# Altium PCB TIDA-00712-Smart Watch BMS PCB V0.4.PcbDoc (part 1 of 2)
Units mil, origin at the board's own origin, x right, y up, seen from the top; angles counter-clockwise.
Board outline 1150 x 800 mil, 2 copper layers (Top Layer, Bottom Layer), stack 11.461 mil thick; 83 components, 53 nets, 288 pads, 152 vias.
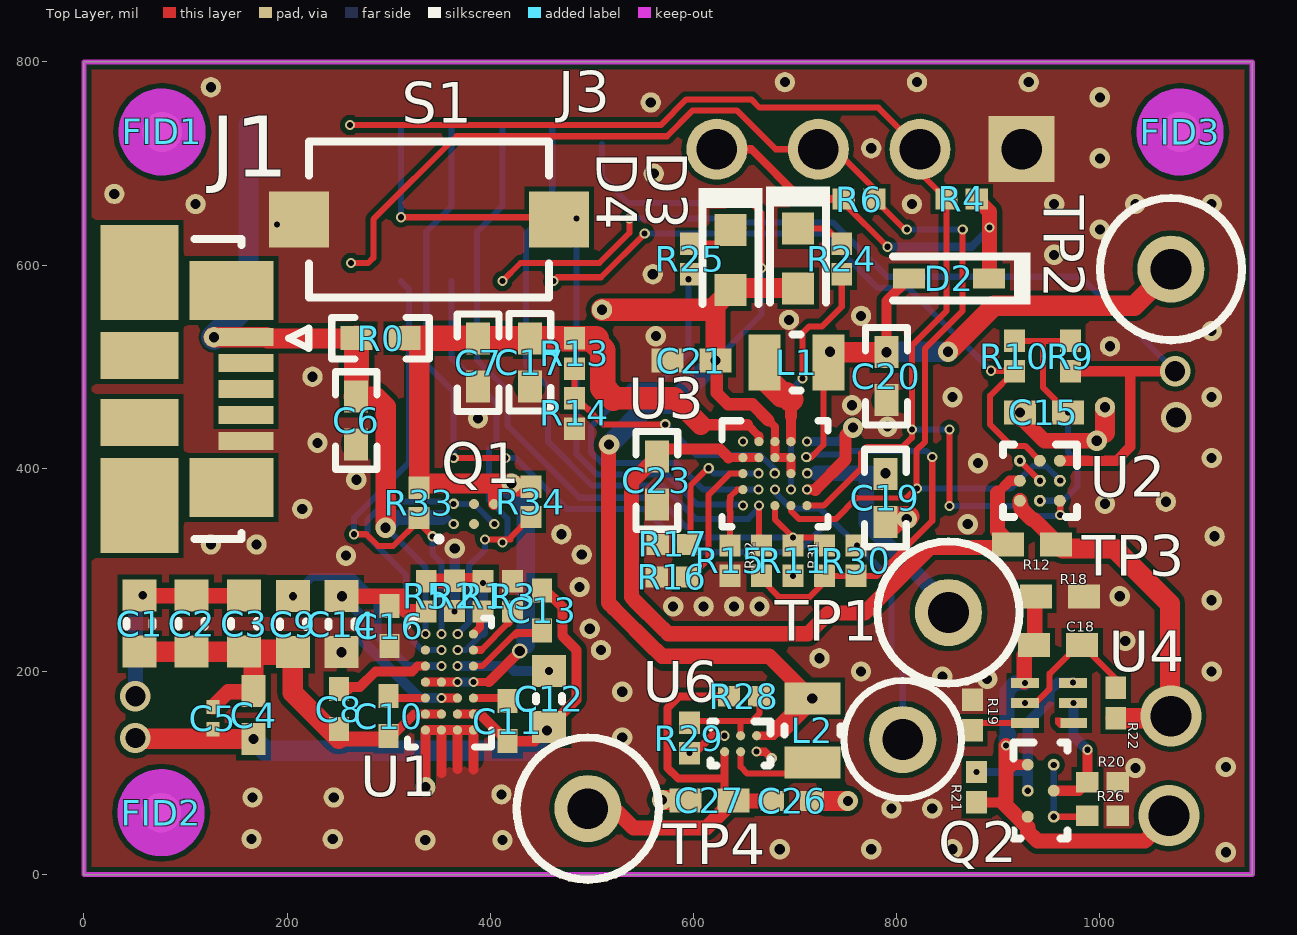
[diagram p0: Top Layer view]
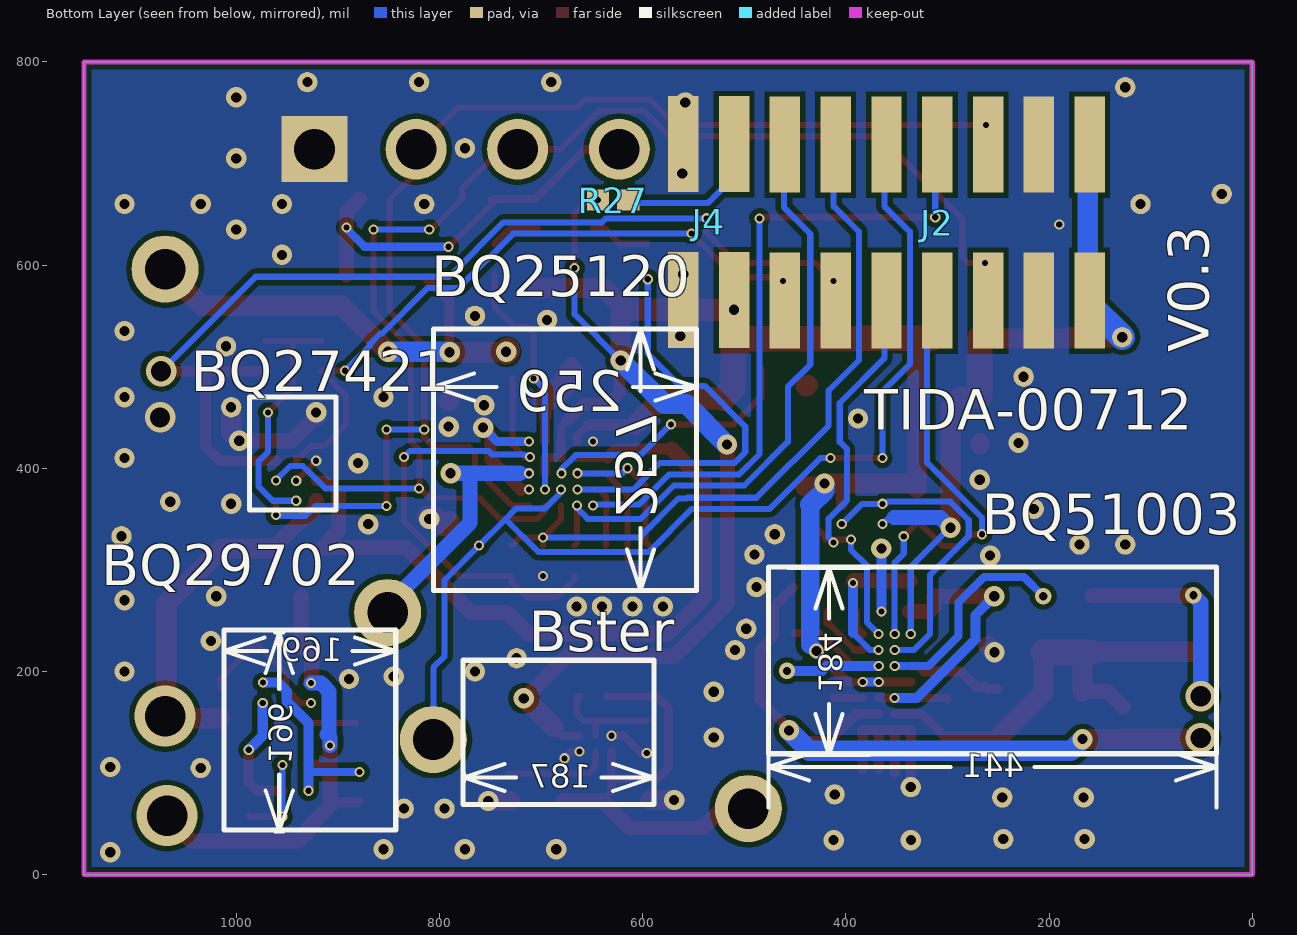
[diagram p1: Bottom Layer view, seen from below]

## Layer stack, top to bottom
Top Solder: solder mask 0.4, Solder Resist, Dk 3.5
Top Layer: signal copper 1.4
Dielectric1: core 8.661, FR-4, Dk 4.8
Bottom Layer: signal copper 1.4
Bottom Solder: solder mask 0.4, Solder Resist, Dk 3.5

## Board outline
0,0 1150,0 1150,800 0,800

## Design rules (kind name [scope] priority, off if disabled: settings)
AcuteAngle [All] p1: minimum=4.50000000000000E+0001 checktracksonly=FALSE
AssemblyTestPointUsage [All] p1: valid=2
Clearance Clearance_Keepouts [All] p1: gap=5
Clearance Clearance_BoardEdge_MountingHoles [All] p2: gap=5
Clearance Clearance_BoardEdge_Poly [All] p3: gap=5
Clearance Clearance_BoardEdge [All] p4: gap=4 except(0: Via-Via Poly-Poly SMDPad-Via Arc-Via Track-Via THPad-Via)
Clearance Clearance_Poly [All] p5: gap=5
ComponentClearance ComponentClearance_MountingHoles_FiducialMarks [InComponentClass('Mounting Holes') vs InComponentClass('FiducialMark')] p1: gap=50 collisioncheckmode=3 verticalgap=10 showdistances=FALSE
ComponentClearance ComponentClearance_Shunt [InComponentClass('Header') vs InComponentClass('Shunt')] p2: gap=50 collisioncheckmode=3 verticalgap=0 showdistances=FALSE
ComponentClearance ComponentClearance_Logo [InComponentClass('Logo')] p3: gap=10 collisioncheckmode=3 verticalgap=10 showdistances=FALSE
ComponentClearance ComponentClearance_ScrewToNut [(HasFootprint('NY PMS 440 0025 PH')) vs (HasFootprint('Keystone_1902C'))] p4: gap=50 collisioncheckmode=3 verticalgap=10 showdistances=FALSE
ComponentClearance ComponentClearance_MountingHoles [InComponentClass('Mounting Holes')] p5: gap=10 collisioncheckmode=3 verticalgap=100000 showdistances=FALSE
ComponentClearance ComponentClearance_SmallPassives [HasFootprint('0201*') or HasFootprint('0402*') or HasFootprint('0508') or HasFootprint('0603*') or HasFootprint('0612') or HasFootprint('0805*') or HasFootprint('0815*') or HasFootprint('0830*') or HasFootprint('1206*') or HasFootprint('1210*') or HasFootprint('1808*') or HasFootprint('1812*') or HasFootprint('1825*') or HasFootprint('2010*') or HasFootprint('2220*') or HasFootprint('2225*') or HasFootprint('2512*') or HasFootprint('2728*') or HasFootprint('3518*') vs HasFootprint('0201*') or HasFootprint('0402*') or HasFootprint('0508') or HasFootprint('0603*') or HasFootprint('0612') or HasFootprint('0805*') or HasFootprint('0815*') or HasFootprint('0830*') or HasFootprint('1206*') or HasFootprint('1210*') or HasFootprint('1808*') or HasFootprint('1812*') or HasFootprint('1825*') or HasFootprint('2010*') or HasFootprint('2220*') or HasFootprint('2225*') or HasFootprint('2512*') or HasFootprint('2728*') or HasFootprint('3518*')] p6: gap=10 collisioncheckmode=3 verticalgap=10 showdistances=FALSE
ComponentClearance ComponentClearance_THtoSMT [IsThruComponent vs IsSMTComponent] p7: gap=10 collisioncheckmode=3 verticalgap=30 showdistances=FALSE
ComponentClearance ComponentClearance_THtoTH [IsThruComponent vs IsThruComponent] p8: gap=10 collisioncheckmode=3 verticalgap=30 showdistances=FALSE
ComponentClearance [All] p9: gap=5 collisioncheckmode=3 verticalgap=10 showdistances=FALSE
DiffPairsRouting [All] p1: maxlimit=100 minlimit=10 mostfreqgap=10 toplayer_minwidth=15 toplayer_maxwidth=15 toplayer_prefwidth=15 bottomlayer_minwidth=15 bottomlayer_maxwidth=15 bottomlayer_prefwidth=15 maxuncoupledlength=1000
FabricationTestPointUsage TestPointUsage [All] p1: valid=2 allowmultiple=FALSE
FabricationTestpoint Testpoint [All] p1: side=3 testpointundercomponent=TRUE minsize=40 maxsize=100 preferedsize=60 minholesize=0 maxholesize=40 preferedholesize=32 testpointgrid=1 allowsidetop=TRUE allowsidebottom=TRUE usegrid=TRUE gridtolerance=0.01
FanoutControl Fanout_LCC [IsLCC] p1: bgadir=Out bgaviamode=Centered fanoutstyle=Auto fanoutdirection=Alternating viagrid=1 // Fanout_LCC (Default Rule)
FanoutControl Fanout_BGA [IsBGA] p2: bgadir=Out bgaviamode=Centered fanoutstyle=Auto fanoutdirection=Alternating viagrid=1 // Fanout_BGA (Default Rule)
FanoutControl Fanout_Default [All] p4: bgadir=Out bgaviamode=Centered fanoutstyle=Auto fanoutdirection=Alternating viagrid=1 // Fanout_Default (Default Rule)
FanoutControl Fanout_Small [(CompPinCount < 5)] p5: bgadir=Out bgaviamode=Centered fanoutstyle=Auto fanoutdirection=OutThenIn viagrid=1 // Fanout_Small (Default Rule)
HoleSize [All] p1: absolutevalues=TRUE maxlimit=251 minlimit=8 maxpercent=80.000 minpercent=20.000
MinimumAnnularRing MinimumAnnularRing_ThermalPadVias [IsVia and InAnyComponent] p1: minimumring=5.91
MinimumAnnularRing [All] p2: minimumring=9
MinimumSolderMaskSliver MinimumSolderMaskSliver_Logo [InComponentClass('Logo') vs InComponentClass('Logo')] p1: minsoldermaskwidth=0.7
MinimumSolderMaskSliver [All] p2: minsoldermaskwidth=3.94
PlaneClearance [All] p1: clearance=10
PlaneConnect [All] p1: planeconnectstyle=Relief reliefexpansion=10 reliefentries=4 reliefconductorwidth=10 reliefairgap=10
PolygonConnect [All] p1: connectstyle=Direct reliefconductorwidth=10 reliefentries=4 polygonreliefangle="90 Angle" airgapwidth=5
RoutingVias ThermalPadVias [IsVia and InAnyComponent] p1: holewidth=6 width=20 viastyle="Through Hole" minholewidth=6 minwidth=20 maxholewidth=15 maxwidth=30
RoutingVias [All] p2: holewidth=6 width=15 viastyle="Through Hole" minholewidth=6 minwidth=10 maxholewidth=10 maxwidth=15
SilkToBoardRegionClearance [Not ((IsComment or IsDesignator) And (Hide <> 'False')) and not InRegion(1000,500,4000,800)] p1:
SilkToSilkClearance SilkToSilkClearance_Pb-FreeLogo [(HasFootprint('Pb-Free_Overlay_Medium') OR HasFootprint('Pb-Free_Overlay_Small')) vs (HasFootprint('Pb-Free_Overlay_Medium') OR HasFootprint('Pb-Free_Overlay_Small'))] p1: silktosilkclearance=0
SilkToSilkClearance [All] p2: silktosilkclearance=4
SilkToSolderMaskClearance "Silk to Solder Mask Opening" [All] p1: minsilkscreentomaskgap=4 clearancetoexposedcopper=FALSE
SolderMaskExpansion [All] p1: expansion=1.97
UnpouredPolygon [All] p1: allowunpoured=FALSE
Width [All] p1: maxlimit=100 minlimit=6 preferedwidth=10 checkconnectedcopper=TRUE
13 further rules are at their usual default settings.

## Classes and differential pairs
component class Header: J2 J4
component class "TIDA-00712-Smart Watch BMS SCH V0.3": C1 C2 C3 C4 C5 C6 C7 C8 C9 C10 C11 C12 C13 C14 C15 C16 C17 C18 C19 C20 C21 C23 C26 C27 D2 D3 D4 J1 J2 J3 J4 L1 L2 Q1 Q2 R0 R1 R2 R3 R4 R5 R6 R8 R9 R10 R11 R12 R13 R14 R15 R16 R17 R18 R19 R20 R21 R22 R24 R25 R26 R27 R28 R29 R30 R31 R32 R33 R34 S1 TP1 TP2 TP3 TP4 U1 U2 U3 U4 U6
component class FiducialMark: FID1 FID2 FID3
component class AssemblyNote: ZZ1 ZZ2 ZZ3
component class "TIDA-00712-Smart Watch BMS Hardwere V0.3": FID1 FID2 FID3 ZZ1 ZZ2 ZZ3

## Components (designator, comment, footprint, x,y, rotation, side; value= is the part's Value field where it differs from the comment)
C1 "GRM188R71E683KA01D" 0603L 55,247 r90 top
C2 "GRM188R71E683KA01D" 0603L 106,247 r90 top
C3 "06033C473JAT2A" 0603L 157.75,247 r90 top
C4 "GRM155R71H182KA01D" 0402 167,157 r270 top
C5 "GRM033R71E101KA01D" 0201L 127,154 r90 top
C6 "GRM155R61C475ME11D" 0402 268,447 r270 top
C7 "CL05A106MP5NUNC" 0402 388,504 r270 top
C8 "GRM155R71E223KA61D" 0402L 251,163 r270 top
C9 "GRM188R71E474KA12D" 0603L 205.75,246.5 r270 top
C10 "GRM155R71E103KA01D" 0402L 300,156 r270 top
C11 "GRM155R71E103KA01D" 0402L 417,151 r270 top
C12 "GRM188R71E474KA12D" 0603L 458,173 r270 top
C13 "GRM155R71E223KA61D" 0402L 451,260 r90 top
C14 "EMK107BBJ106MA-T" 0603L 253.75,246.5 r90 top
C15 "GRM155R60J474KE19D" 0402 945,455 r180 top
C16 "GRM188R61C475KAAJ" 0402L 300.75,244.5 r270 top
C17 "GRM155R61A105KE15D" 0402 439,504.24 r270 top
C18 "GRM155R61A105KE15D" 0402 959,226 r180 top
C19 "CL05A106MP5NUNC" 0402 789,370.75 r270 top
C20 "CL05A106MP5NUNC" 0402 790,490.62 r270 top
C21 "GRM155R61C475ME11D" 0402 598,506 r0 top
C23 "GRM155R61A105KE15D" 0402 564,388 r270 top
C26 "GRM188R61C475KAAJ" 0402L 697,72.49 r0 top
C27 "GRM155R71C104KA88D" 0402 616,73 r180 top
D2 "1N4148WT" Fairchild_SOD-523F 851.63,587 r180 top
D3 "LTST-C190GKT" LED_LTST-C190 703,606.53 r90 top
D4 "LTST-C190CKT" LED_LTST-C190_Red 636.44,605 r90 top
FID1 "Fiducial" Fiducial10-20 77,731 r0 top
FID2 "Fiducial" Fiducial10-20 76,61 r0 top
FID3 "Fiducial" Fiducial10-20 1079,731 r0 top
J1 "47346-1001" Molex_47346-1001 -2.09,477.97 r270 top
J2 "20021121-00014T4LF" FCI_20021121-00014x4 310,641.77 r270 bottom
J3 "" CONN_22-05-3041 773,938.41 r180 top
J4 "20021121-00004C4LF" FCI_20021121-00004C4LF 535,642.23 r270 bottom
L1 "MDT2012-CLR2R2AM" MDT2012-CLR 701.5,504 r0 top
L2 "MDT2012-CLR2R2AM" MDT2012-CLR 717,142 r270 top
Q1 "CSD75208W1015" YZC0006ABBB 384,355 r90 top
Q2 "CSD83325L" YJE0006A 941.83,82.59 r0 top
R0 "CRCW04024K99FKED" 0402 292,528 r0 top
R1 "CRCW0201845RFKED" 0201M 393,274 r90 top
R2 "CRCW0201196RFKED" 0201M 364.75,274.5 r90 top
R3 "MCR006YRTF1002" 0201M 422,274 r270 top
R4 "CRCW020120K0FKED" 0201M 864,665 r180 top
R5 "CRCW020120K0FKED" 0201M 337,274 r90 top
R6 "CRCW020120K0FKED" 0201M 763,665 r0 top
R9 "CRCW020120K0FKED" 0201M 971,510.44 r270 top
R10 "CRCW020120K0FKED" 0201M 916,510.44 r270 top
R11 "CRCW020120K0FKED" 0201M 698,308.96 r90 top
R12 "CRCW04024K99FKED" 0402 933,325 r0 top
R13 "CRCW020120K0FKED" 0201M 483,513 r90 top
R14 "CRCW020120K0FKED" 0201M 483,454 r90 top
R15 "CRCW020120K0FKED" 0201M 636,308.96 r90 top
R16 "CRCW020120K0FKED" 0201M 579,293 r0 top
R17 "CRCW020120K0FKED" 0201M 580,325 r0 top
R18 "CRCW04024K99FKED" 0402 960.62,274 r180 top
R19 "CRCW020120K0FKED" 0201M 874.62,157.08 r270 top
R20 "CRCW020120K0FKED" 0201M 1002.62,91 r180 top
R21 "CRCW020120K0FKED" 0201M 878.62,86.04 r270 top
R22 "CRCW020120K0FKED" 0201M 1015.62,169 r90 top
R24 "CRCW020120K0FKED" 0201M 746,606 r90 top
R25 "CRCW020120K0FKED" 0201M 597,606 r90 top
R26 "ERJ-1GEJ1R2C" 0201M 1002.66,58 r0 top
R27 "ERJ-1GEJ1R2C" 0201M 629,664 r180 bottom
R28 "CRCW020120K0FKED" 0201M 650,175.49 r180 top
R29 "CRCW020120K0FKED" 0201M 596,134.49 r90 top
R30 "CRCW020120K0FKED" 0201M 760,309.04 r90 top
R31 "CRCW020120K0FKED" 0201M 729,308.96 r90 top
R32 "CRCW020120K0FKED" 0201M 667,308.96 r270 top
R33 "CRCW020120K0FKED" 0201M 330,366 r270 top
R34 "CRCW020120K0FKED" 0201M 440,367 r270 top
S1 "434121025816" SW_434121025816 339.95,645 r0 top
TP1 "5003" Keystone5003 806,133 r0 top
TP2 "5005" Keystone5005 1070,596 r0 top
TP3 "5005" Keystone5005 851,258 r0 top
TP4 "5005" Keystone5005 496,65 r0 top
U1 "BQ51003YFPR" YFP0028APAL 359.75,189.5 r180 top
U2 "BQ27421YZFR-G1B" YZF0009AKAL 941,387.68 r270 top
U3 "BQ25120YFF" YFF0025AWAW 680.2,394.67 r0 top
U4 "BQ29702DSER" DSE0006A 950.08,169 r180 top
U6 "TPS61046YFFR" YFF0006AAAA 646.47,128.86 r270 top
ZZ1 "These assemblies are ESD sensitive, ESD precautions shall be observed." AssemblyNote 185,3829.11 r0 top
ZZ2 "These assemblies must be clean and free from flux and all contaminants. Use of no clean flux is not acceptable." AssemblyNote 185,3740.56 r0 top
ZZ3 "These assemblies must comply with workmanship standards IPC-A-610 Class 2, unless otherwise specified." AssemblyNote 185,3652 r0 top

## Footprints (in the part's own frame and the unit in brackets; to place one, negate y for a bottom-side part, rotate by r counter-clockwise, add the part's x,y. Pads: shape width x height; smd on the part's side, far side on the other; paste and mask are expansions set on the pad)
0201L [mm] "Data from Kemet datasheet CC101_COM dated 7/28/11"
  rect 0.36x0.32 smd mask+0.048: 1(-0.28,0) 2(0.28,0)
  body extent -0.31,-0.16 0.31,0.16, height 0.26
0201M [mm] "Data from Kemet datasheet CC101_COM dated 7/28/11"
  rect 0.56x0.52 smd mask+0.048: 1(-0.38,0) 2(0.38,0)
  body extent -0.31,-0.16 0.31,0.16, height 0.26
0402 [mm] "0402 from SM-752 data"
  rect 0.8x0.6 smd: 1(-0.6,0) 2(0.6,0)
  body extent -0.55,-0.3 0.55,0.3, height 0.6
0402L [mm] "0402 from SM-752 data"
  rect 0.6x0.5 smd: 1(-0.5,0) 2(0.5,0)
  body extent -0.55,-0.3 0.55,0.3, height 0.6
0603L [mm] "0603 from SM-752 data"
  rect 0.8x0.85 smd: 1(-0.7,0) 2(0.7,0)
  silkscreen extent -0.07,-0.33 0.07,0.33, body extent -0.87,-0.47 0.87,0.47, height 0.85
AssemblyNote [mil] "Assembly Note"
CONN_22-05-3041 [mil] "MOLEX"
  rect 64.96x64.96 hole 40: 1(-150,224.41)
  round 60 hole 40: 2(-50,224.41) 3(50,224.41) 4(150,224.41)
  body extent -197,-272 197,237, height 251
DSE0006A [mm] "TI recommended land pattern"
  rect 0.66x0.25 smd: 1(-0.62,0.5)
  rect 0.7x0.25 smd: 2(-0.6,0) 3(-0.6,-0.5) 4(0.6,-0.5) 5(0.6,0) 6(0.6,0.5)
  Top Layer region: -0.3,0.625 -0.25,0.625 -0.15,0.525 -0.15,0.375 -0.3,0.375
  body extent -0.77,-0.77 0.77,0.77, height 0.8
Fairchild_SOD-523F [mm] "SMD, 2-Leads, Body 1.2x0.8mm"
  rect 0.8x0.5 smd: 1(-1,0) 2(1,0)
  silkscreen extent -2.03,-0.65 1.4,0.65, body extent -0.65,-0.45 0.65,0.45, height 0.7
FCI_20021121-00004C4LF [mm] "SMD, 4-Leads, Body 2.54x3.4mm, Pitch 1.27mm"
  rect 2.4x0.76 smd: 1(-1.95,0.635) 2(1.95,0.635) 3(-1.95,-0.635) 4(1.95,-0.635)
  body extent -2.8,-1.27 2.7,1.27, height 4.5
FCI_20021121-00014x4 [mm] "Header, 1.27mm, 7x2, SMT"
  rect 2.4x0.76 smd: 1(-1.95,3.81) 2(1.95,3.81) 3(-1.95,2.54) 4(1.95,2.54) 5(-1.95,1.27) 6(1.95,1.27) 7(-1.95,0) 8(1.95,0) 9(-1.95,-1.27) 10(1.95,-1.27) 11(-1.95,-2.54) 12(1.95,-2.54) 13(-1.95,-3.81) 14(1.95,-3.81)
  body extent -2.75,-4.45 2.75,4.44, height 4.5
Fiducial10-20 [mm]
  round 1 smd mask+0.5: 1(0,0)
  Top Layer keep-out circle w1.178: c0,0 r0.5
Keystone5003 [mil] "For Keystone 500x miniature loop terminals"
  round 66 hole 40: 1(0,0)
  silkscreen extent -58,-58 58,58, body extent -49,-49 49,49, height 182
Keystone5005 [mil] "Keystone Compact loops"
  round 66 hole 40: 1(0,0)
  silkscreen extent -70,-70 70,70, body extent -63,-63 62,63, height 225
LED_LTST-C190 [mm] "Lite-On"
  rect 0.8x0.8 smd: 1(-0.75,0) 2(0.75,0)
  silkscreen extent -1.1,-0.8 1.8,0.8, body extent -0.85,-0.45 0.85,0.45, height 0.9
LED_LTST-C190_Red [mm] "Lite-On"
  rect 0.8x0.8 smd: 1(-0.75,0) 2(0.75,0)
  silkscreen extent -1.1,-0.8 1.8,0.8, body extent -0.85,-0.45 0.85,0.45, height 0.9
MDT2012-CLR [mm] "SMD, 2-Leads, Body 2.15x1.4mm, Height 0.58mm"
  rect 0.8x1.4 smd: 1(-0.8,0) 2(0.8,0)
  silkscreen extent -0.1,-0.7 0.1,0.7, body extent -1.08,-0.7 1.07,0.7, height 0.58
Molex_47346-1001 [mm] "Receptacle, 0.65mm, 5x1, R/A, SMT"
  rect 0.45x1.38 smd: 1(-1.3,4.11) 2(-0.65,4.11) 3(0,4.11) 4(0.65,4.11) 5(1.3,4.11)
  rect 1.475x2.1 smd: 6(-2.462,3.75) 7(2.462,3.75)
  rect 2.375x1.95 smd: 8(-2.913,1.45) 11(2.913,1.45)
  rect 1.175x1.95 smd: 9(-0.837,1.45) 10(0.837,1.45)
  silkscreen extent -3.75,2.83 3.75,5.67, body extent -3.9,-0.7 3.9,4.3, height 2.68
SW_434121025816 [mm] "SMD, 2-Leads, Body 6x3.9mm, Pitch 6.5mm"
  rect 1.5x1.4 smd: 1(-3.25,0) 2(3.25,0)
  silkscreen extent -3,-1.95 3,1.95, body extent -3.65,-1.95 3.65,1.95, height 2.5
YFF0006AAAA [mm] "DSBGA, 6-Leads, Body 0.8x1.2mm, Pitch 0.4mm"
  round 0.23 smd paste-0.13 mask+0.038: A1(-0.2,0.4) A2(0.2,0.4) B1(-0.2,0) B2(0.2,0) C1(-0.2,-0.4) C2(0.2,-0.4)
  silkscreen extent -0.55,-0.75 0.55,0.75, body extent -0.41,-0.61 0.41,0.61, height 0.63
YFF0025AWAW [mm] "TI WCSP 2.45x2.45mm"
  round 0.23 smd paste-0.13 mask+0.04: A1(-0.8,0.8) A2(-0.4,0.8) A3(0,0.8) A4(0.4,0.8) A5(0.8,0.8) B1(-0.8,0.4) B2(-0.4,0.4) B3(0,0.4) B4(0.4,0.4) B5(0.8,0.4) C1(-0.8,0) C2(-0.4,0) C3(0,0) C4(0.4,0) C5(0.8,0) D1(-0.8,-0.4) D2(-0.4,-0.4) D3(0,-0.4) D4(0.4,-0.4) D5(0.8,-0.4) E1(-0.8,-0.8) E2(-0.4,-0.8) E3(0,-0.8) E4(0.4,-0.8) E5(0.8,-0.8)
  silkscreen extent -1.33,-1.33 1.33,1.33, body extent -1.22,-1.22 1.22,1.22, height 0.64
YFP0028APAL [mm] "BGA, 28-Leads, Body 3.046x1.923mm,  Pitch 0.4mm"
  round 0.23 smd paste-0.2 mask+0.04: A1(-0.6,1.2) A2(-0.2,1.2) A3(0.2,1.2) A4(0.6,1.2) B1(-0.6,0.8) B2(-0.2,0.8) B3(0.2,0.8) B4(0.6,0.8) C1(-0.6,0.4) C2(-0.2,0.4) C3(0.2,0.4) C4(0.6,0.4) D1(-0.6,0) D2(-0.2,0) D3(0.2,0) D4(0.6,0) E1(-0.6,-0.4) E2(-0.2,-0.4) E3(0.2,-0.4) E4(0.6,-0.4) F1(-0.6,-0.8) F2(-0.2,-0.8) F3(0.2,-0.8) F4(0.6,-0.8) G1(-0.6,-1.2) G2(-0.2,-1.2) G3(0.2,-1.2) G4(0.6,-1.2)
  silkscreen extent -1.05,-1.6 1.05,1.63, body extent -0.96,-1.52 0.96,1.52, height 0.51
YJE0006A [mm] "LGA, 6-Leads, Body 2.16x1.11mm, Pitch 0.65mm"
  round 0.3 smd paste-0.15 mask+0.05: A1(-0.325,0.65) A2(0.325,0.65) B1(-0.325,0) B2(0.325,0) C1(-0.325,-0.65) C2(0.325,-0.65)
  silkscreen extent -0.67,-1.2 0.67,1.2, body extent -0.57,-1.1 0.57,1.1, height 0.23
YZC0006ABBB [mm] "DSBGA"
  round 0.25 smd paste-0.125 mask+0.05: A1(-0.25,0.5) A2(0.25,0.5) B1(-0.25,0) B2(0.25,0) C1(-0.25,-0.5) C2(0.25,-0.5)
  silkscreen extent -0.68,0.82 -0.58,0.93, body extent -0.5,-0.75 0.5,0.75, height 0.62
YZF0009AKAL [mm] "BGA, 9-Leads, Body 1.6205x1.58mm, Pitch 0.5mm"
  round 0.3 smd paste-0.15 mask+0.05: A1(-0.5,0.5) A2(0,0.5) A3(0.5,0.5) B1(-0.5,0) B2(0,0) B3(0.5,0) C1(-0.5,-0.5) C2(0,-0.5) C3(0.5,-0.5)
  silkscreen extent -0.9,-0.93 0.9,0.93, body extent -0.8,-0.83 0.8,0.83, height 0.63

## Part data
C1 C2: "CAP, CERM, 0.068uF, 25V, +/-10%, X7R, 0603"
C3: "CAP, CERM, 0.047uF, 25V, +/-5%, X7R, 0603"
C4: "CAP, CERM, 1800 pF, 50 V, +/- 10%, X7R, 0402"
C5: "CAP, CERM, 100pF, 25V, +/-10%, X7R, 0201"
C6 C21: "CAP, CERM, 4.7 µF, 16 V, +/- 20%, X5R, 0402"
C7 C19 C20: "CAP, CERM, 10 µF, 10 V, +/- 20%, X5R, 0402"
C8 C13: "CAP, CERM, 0.022uF, 25V, +/-10%, X7R, 0402"
C9 C12: "CAP, CERM, 0.47uF, 25V, +/-10%, X7R, 0603"
C10 C11: "CAP, CERM, 0.01uF, 25V, +/-10%, X7R, 0402"
C14: "CAP, CERM, 10uF, 16V, +/-20%, X5R, 0603"
C15: "CAP, CERM, 0.47 µF, 6.3 V, +/- 10%, X5R, 0402"
C16 C26: "CAP, CERM, 4.7uF, 16V, +/-10%, X5R, 0603"
C17 C23: "CAP, CERM, 1 µF, 10 V, +/- 10%, X5R, 0402"
C18: "CAP, CERM, 0.1µF, 10 V, +/- 10%, X5R, 0402"
C27: "CAP, CERM, 0.1 µF, 16 V, +/- 10%, X7R, 0402"
D2: "Diode, Switching, 75 V, 0.3 A, SOD-523F"
D3: "LED, Green, SMD"
D4: "LED, Red, SMD"
FID1 FID2 FID3: "Fiducial mark.  There is nothing to buy or mount."
J1: "Receptacle, Micro-USB Type B, 0.65 mm, 5x1, R/A, Bottom Mount SMT"
J2: "Header, 1.27 mm, 7x2, Au, SMT"
J3: library part 22-05-3041, "Header (friction lock), 100mil, 4x1, R/A, TH"
J4: "Header, 50mil, 2x2, Tin, SMD"
L1 L2: "Inductor, Multilayer, 2.2 µH, 1.35 A, 0.23 ohm, SMD"
Q1: "MOSFET, P-CH, -20 V, -1.6 A,"
Q2: "MOSFET, N-CH,  V,  A,"
R0: "RES, 0 Ohm 1%, 0.063 W, 0402"
R1: "RES, 805, 1%, 0.05 W, 0201"
R2: "RES, 196, 1%, 0.05 W, 0201"
R3: "RES, 10.0 k, 1%, 0.05 W, 0201"
R4 R5 R6 R9 R10 R11 R13 R14 R15 R16 R17 R24 R25 R30 R31 R32 R33 R34: "RES, 20.0 k, 1%, 0.05 W, 0201"
R12 R18: "RES, 0 Ohm, 1%, 0.063 W, 0402"
R19: "RES, 2.2K, 1%, 0.05 W, 0201"
R20 R21: "RES, 5.1M, 1%, 0.05 W, 0201"
R22: "RES, 330, 1%, 0.05 W, 0201"
R26 R27: "RES, 1.2, 5%, 0.05 W, 0201"
R28: "RES, 1M, 1%, 0.05 W, 0201"
R29: "RES, 71.5K 1%, 0.05 W, 0201"
S1: "Switch, Tactile, SPST, 12 V, SMD"
TP1: "Test Point, Miniature, Orange, TH"
TP2 TP3 TP4: "Test Point, Compact, Red, TH"
U1: "Highly Integrated Wireless Receiver Qi (WPC v1.1) Compliant Power Supply, YFP0028APAL"
U2: "System-Side Impedance Track Fuel Gauge With Integrated Sense Resistor, YZF0009AKAL"
U3: "YFF0025AWAW"
U4: "Cost-Effective Voltage and Current Protection Integrated Circuit for Single-Cell Li-Ion/Li-Polymer Batteries, DSE0006A"
U6: "28-V Output Voltage Boost Converter in WCSP Package, YFF0006AAAA"
ZZ1 ZZ2 ZZ3: library part AssemblyNote

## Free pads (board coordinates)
  round 20 hole 10: 0(110,660) 0(125,325) 0(128,529) 0(225,490) 0(336.13,86.13) 0(470,335) 0(488,283) 0(498,242) 0(509,221) 0(510,556) 0(558,760) 0(561,690) 0(610,264) 0(694,546) 0(724,213) 0(795,65) 0(815,660) 0(930,780) 0(1005,460) 0(1010,520) 0(1035,105) 1(170,325) 1(411,79) 1(490,315) 1(560,591) 1(640,264) 1(775,715) 1(820,780) 1(835,65) 1(1065,367) 2(125,775) 2(215,360) 2(690,780) 2(765,550) 2(1113,333) 3(30,670) 4(246,76) 5(245,35)

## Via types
v1: diameter 10, hole 6, Top Layer to Bottom Layer, 77 vias
v2: diameter 20, hole 10, Top Layer to Bottom Layer, 61 vias
v3: diameter 10, hole 6, Top Layer to Bottom Layer, tented bottom, 4 vias
v4: diameter 30, hole 20, Top Layer to Bottom Layer, 4 vias
v5: diameter 16, hole 8, Top Layer to Bottom Layer, tented bottom, 3 vias
v6: diameter 60, hole 40, Top Layer to Bottom Layer, 2 vias
v7: diameter 15, hole 10, Top Layer to Bottom Layer, 1 vias

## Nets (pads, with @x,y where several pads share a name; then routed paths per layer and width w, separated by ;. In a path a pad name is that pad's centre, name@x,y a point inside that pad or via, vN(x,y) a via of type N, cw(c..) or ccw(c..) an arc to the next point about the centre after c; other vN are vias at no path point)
BAT: C23.1 R12.1 U2.C2 U3.B1 U3.B2 | length 771
  Top Layer w9: 634.58,410.42 U3.B1@648.71,410.42 U3.B2@664.46,410.42
  Top Layer w10: 899.32,375.68 911.32,387.68 U2.C2@921.32,387.68
  Top Layer w11: C23.1@571.76,419 626,419 634.58,410.42
  Top Layer w15: C23.1@571.76,419 539,386.24 539,273.28 541.54,270.74 541.54,270.46 570.5,241.5 570.78,241.5 575.28,237 712.53,237 733.03,257.5 768.5,257.5 833,322 R12.1@915.38,322 ; 899.32,375.68 899.32,338.06 R12.1@915.38,322 ; R12.1@916.38,321 R12.1@915.38,322
BIN: J2.14 R10.2 U2.B1 | length 659.4
  Top Layer w6: v1(462,584.23) 465.77,588 509,588 v1(552,631) ; v1(893,496) 915.48,496 R10.2@916,495.48 892,471.48 892,443 913,422 926.37,422 U2.B1@941,407.37 U2.B1@941,410.08
  Bottom Layer w6: v1(552,631) 727.48,631 781,577.47 811.53,577.47 856.38,532.62 858.08,532.62 868.62,522.08 868.62,520.38 v1(893,496)
CD: J2.13 R32.1 U3.E2 | length 618.2
  Top Layer w6: v1(664.46,363.17) 664.46,326.46 R32.1@667,323.92
  Bottom Layer w6: J2.13@462,737.77 461,736.77 461,656.75 435,630.75 435,502 457,480 457,426 500,383 569.25,383 602.08,350.17 654.09,350.17 664.46,360.54 v1(664.46,363.17)
CELL+: R12.2 R22.1 U2.C3 | length 351
  Top Layer w15: U2.C3@921.32,368 921.32,363.31 922.59,362.03 922.59,360.38 933.38,349.59 935.03,349.59 R12.2@963.62,321
  Top Layer w20: R12.2@963.62,321 1014.62,321 1069,266.62 1069,168.38 1054.66,154.04 R22.1@1015.62,154.04
  other v6: 1070,156
CELL-: C18.2 Q2.A1 Q2.C1 R18.2 R21.2 U4.4 | length 468.9
  Top Layer w10: R21.2@879.7,72 880.7,71 904.62,71 ; 907.62,100 915.8,108.18 Q2.A1@929.03,108.18 ; U4.4@925.62,189.52 v1(926.46,188.69)
  Top Layer w15: v1(907.62,127) 907.62,100 907.62,74 904.62,71 929.03,46.59 929.03,42.59 938.62,33 1044.38,33 1069.38,58 v6(1068,58) ; U4.4@925.62,189.52 925.62,216.24 C18.2@935.38,226 ; C18.2@936,226.62 R18.2@936,274
  Top Layer w20: C18.2@935.38,226 C18.2@936,226.62
  Bottom Layer w15: v1(907.62,127) 907.62,135 910.62,138 908.62,140 908.62,180.22 911.58,183.18 911.58,183.76 916.51,188.69 v1(926.46,188.69)
COIL1: C1.2 C2.2 C3.2 | length 203.5
  Top Layer w15: C1.2@57.75,274.56 103,274.56 C3.2@157.75,274.56
  Bottom Layer w15: v4@50.75,174.5 v4(50.75,175.5) 50.75,267.75 v5(58,275)
COIL2: C4.2 C5.1 C11.2 C12.2 C13.2 U1.B1 U1.B2 | length 687.7
  Top Layer w9: U1.B2@367.63,158 U1.B1@383.37,158
  Top Layer w10: U1.B1@383.37,158 390.32,158 C11.2@417,131.31 443.87,131.31 C12.2@458,145.44 484.73,172.17 484.73,221.27 471,235 471,263.69 C13.2@452,282.69
  Top Layer w20: v4(50.75,134.5) 51.48,133.76 126.91,133.76 v2(167,133.38)
  Bottom Layer w20: v2(167,133.38) 178.38,122 436,122 v2(456,142)
EN1: J2.8 R33.2 U1.G3 | length 477.6
  Top Layer w6: v1(266,335) 278.02,335 289.54,323.48 304.46,323.48 R33.2@330,349.02 ; R33.2@330,351.04 R33.2@330,349.02 ; v1(343,333) 330,346 R33.2@330,349.02
  Bottom Layer w6: v1(266,335) 266,351.49 320,405.49 320,576.23 J2.8@312,584.23 ; v1(343,333) 343,316 352,307 v1@352,236.86
  other v1: 351.88,236.74
EN2: J2.10 R34.2 U1.G2 | length 448.4
  Top Layer w6: v1(395,330) 420,330 418.98,331.02 R34.2@440,352.04
  Bottom Layer w6: J2.10@362,584.23 362,508.22 406,464.22 406,426 398.76,418.76 398.76,368.62 417,350.38 417,332 v1(412,327) ; v1(368,237) 379,248 379,304 395,320 v1(395,330)
GND: C6.2 C7.2 C14.1 C15.2 C16.2 C17.2 C19.2 C20.2 C21.1 C23.2 C26.2 C27.2 J1.5 J2.3 J2.4 J3.1 J4.3 J4.4 pad.0@110,660 pad.0@125,325 pad.0@225,490 pad.0@336.13,86.13 pad.0@470,335 pad.0@488,283 pad.0@498,242 pad.0@509,221 pad.0@558,760 pad.0@561,690 pad.0@610,264 pad.0@694,546 pad.0@724,213 pad.0@795,65 pad.0@815,660 pad.0@930,780 pad.0@1005,460 pad.0@1010,520 pad.0@1035,105 pad.1 pad.2 pad.3 pad.4 pad.5 R2.1 R3.1 R11.1 R14.1 R15.1 R16.1 R17.1 R18.1 R19.1 R20.1 R26.2 R29.1 S1.1 U1.A1 U1.A2 U1.A3 U1.A4 U2.B2 U2.C1 U3.A1 U3.A5 U3.D5 U6.A2 U6.C1 | length 713
  Top Layer w6: v1(921.32,407.37) v1(941,387.68)
  Top Layer w8: v1(596,119.53) 600.96,119.53 601,119.49 618.25,136.74 v1(630.72,136.74) ; U6.A2@662.22,120.99 670.51,120.99 v1(677,114.49)
  Top Layer w10: pad.0@336.13,86.13 U1.A4@336.13,142.25 U1.A3@351.88,142.25 ; 351.88,100 U1.A3@351.88,142.25 ; 367.63,103.98 U1.A2@367.63,142.25 ; 383.37,103.33 U1.A1@383.37,142.25 U1.A2@367.63,142.25 ; v1(711.7,378.92) 719.92,378.92 ; U1.A3@351.88,142.25 U1.A2@367.63,142.25
  Top Layer w12: 719.92,378.92 749.68,408.68 749.68,432.68 v2(757,440)
  Top Layer w15: C15.2@921.38,451.03 945.41,427 v2(997,427)
  Top Layer w20: v2(253.75,218.94) C14.1@259.63,224.81 ; C6.2@268,423.38 C6.2@268,424.76 ; C17.2@437.62,482 C17.2@439,480.62 ; v2(569,73.49) C27.2@592.38,73.49 ; 730.37,72.49 v2(752,72.49) ; C19.2@790,348 795,343 804.75,352.75 812.71,352.75 v2(810,350) ; C20.2@790,467 C20.2@791,466 ; C15.2@921.38,451.03 v2(921.38,455) ; 1005,435 pad.0@1005,460
  Bottom Layer w9: v1(711.7,426.17) 743.17,426.17 v2(757,440)
  Bottom Layer w10: v1(365,259) v2(365,321)
  other v1: 662,121.15 698,294 648.71,426.17 190,640
  other v2: 1124,22 685,25 775,25 855,25 336,34 412,34 165,35 166,76 1124,106 530,135 530,180 889.08,192.5 845,195 765,200 1110,200 1025,230 580,264 665,264 1110,270 1019.62,274 258,314 870,345 1005,365 268.21,388.62 880,405 1110,410 230,425 791,441 388,449 756,462 855,470 1110,470 563,530 1110,535 955,610 1000,635 955,660 1035,660 1110,660 1000,705 1000,765
  other v4: 1075,450
GPOUT: J2.12 R9.2 U2.A1 | length 1011.2
  Top Layer w6: v1(412,584.23) 429.77,602 507.44,602 537,631.56 v1(537,646)
  Top Layer w10: U2.A1@960.68,407.37 988.35,407.37 988.72,407 1005.28,407 1005.65,407.37 1016.37,407.37 1030,421 1030,495.48 ; R9.2@971,495.48 1030,495.48 ; v4(1074,495.48) 1030,495.48
  Bottom Layer w6: v1(537,646) 599.47,646 599.7,645.76 636.49,645.76 640.25,642 737,642 790.53,588.47 981.01,588.47 v4(1074,495.48)
LSCTRL: J2.11 R11.2 R31.2 U3.E3 | length 727.1
  Top Layer w6: U3.E3@680.2,363.17 680.2,349.8 v1(698,332) ; R11.2@698,323.92 v1(698,332) ; R31.2@729,323.92 720.92,332 v1(698,332)
  Bottom Layer w6: J2.11@412,737.77 412,657.75 387.04,632.79 387.04,506.49 417,476.53 417,442 488,371 556.03,371 556.75,370.28 564.72,370.28 602.5,332.5 602,332 v1(698,332)
LSLDO: C19.1 TP3.1 U3.C5 | length 260.4
  Bottom Layer w10: v1(712,395) 721,395
  Bottom Layer w15: 721,395 770,395 ; v2(789,395.06) 788.94,395 770,395 ; TP3.1@865,251 770,346 770,395
MR: J2.7 S1.2 U3.E1 | length 680.9
  Top Layer w6: v1(312,647) S1.2@483.95,647
  Bottom Layer w6: v1(312,647) J2.7@312,737.77 ; v1@483.95,647 v1(485,645.95) 485,414 505,394 573.81,394 603.64,364.17 647.71,364.17 v1(648.71,363.17)
NetC1_1: C1.1 C2.1 C3.1 C4.1 C5.2 C8.2 C9.2 C10.2 U1.B3 U1.B4 | length 454.6
  Top Layer w9: C10.2@300.31,133.31 325,158 U1.B4@336.13,158 U1.B3@351.88,158
  Top Layer w10: C10.2@299.68,133.63 300,133.31 C10.2@300.31,133.31
  Top Layer w15: C5.2@127,165.02 141.98,180 166.38,180 C4.1@167,180.62 ; C8.2@251,133.63 C10.2@299.68,133.63
  Top Layer w20: C1.1@55,219.44 C2.1@106,219.44 157.75,219.44 158.25,218.94 167,210.19 C4.1@167,180.62 ; C9.2@205.75,218.94 205.75,178.88 C8.2@251,133.63
  Top Layer w25: C3.1@158.25,218.94 C9.2@205.75,218.94
NetC8_1: C8.1 U1.E4 | length 94.5
  Top Layer w9: 323,200 328.24,205.24 U1.E4@336.13,205.24
  Top Layer w10: C8.1@251,182.68 260.68,182.68 262.63,184.63 271.63,184.63 287,200 323,200
NetC9_1: C9.1 U1.E3 | length 209.7
  Bottom Layer w8: v5(205.75,274.06) 224.7,293 264.05,293 288.96,268.09 288.96,235.04 318.75,205.25 v3(351.88,205.25)
NetC10_1: C10.1 U1.C4 | length 36.6
  Top Layer w8: C10.1@300,172.68 301.06,173.75 U1.C4@336.13,173.75
NetC11_1: C11.1 U1.C1 | length 29.7
  Top Layer w8: U1.C1@383.37,173.75 412,173.75 C11.1@412.75,174.5
NetC12_1: C12.1 U1.E2 | length 93.4
  Bottom Layer w8: v3(367.62,205.25) v3@368.37,206
  Bottom Layer w10: v3(367.62,205.25) 419.01,205.25 423.69,200.56 v5(458,200.56)
NetC13_1: C13.1 U1.E1 | length 80.2
  Top Layer w6: U1.E1@383.37,205.24 392.32,205.24 423.58,236.5 424.88,236.5
  Top Layer w8: 424.88,236.5 426.38,238 C13.1@450,238
NetC14_2: C14.2 C16.1 R5.1 U1.C2 U1.C3 | length 264.6
  Top Layer w9: U1.C3@351.88,173.75 U1.C2@367.63,173.75
  Top Layer w15: C14.2@253.75,274.06 313.05,274.06 313.05,263.94 317.96,259.04 R5.1@337,259.04
  Bottom Layer w10: v2(254,274) 272.45,255.55 272.45,231.55 330,174 v1(352,174)
NetC18_1: C18.1 R22.2 U4.5 | length 138.6
  Top Layer w6: v1(926.46,169) 936.79,169 950.62,182.84 950.62,197.72 C18.1@977.4,224.5 ; C18.1@982.62,226 1015.62,193 R22.2@1015.62,183.96 ; C18.1@982.76,229.86 C18.1@982.9,230
NetD3_2: D3.2 R24.2 | length 49.3
  Top Layer w6: D3.2@703,636.06 730.91,636.06 R24.2@746,620.96
NetD4_2: D4.2 R25.2 | length 60.4
  Top Layer w6: R25.2@595,620.96 R25.2@597,620.96 622.43,620.96 638,636.53 D4.2@649,636.53
NetL2_2: L2.2 U6.B2 | length 104.2
  Top Layer w6: U6.B2@646.47,120.99 646.47,106.03 653,99.49 L2.2@733,99.49
NetQ1_A2: Q1.A2 Q1.C1 U1.F3 | length 310.9
  Bottom Layer w6: v1(351.88,220.99) 333.01,220.99 317,237 317,295 279,333 279,348.93 297.19,367.13 359.05,367.13 361.17,365 v1(364,365) 384,365 v1(404,345)
NetQ2_A2: Q2.A2 Q2.C2 R26.1 | length 84.5
  Top Layer w6: v1(954.62,57) 986.7,57 R26.1@987.7,58
  Bottom Layer w6: v1(954.62,57) v1(954.62,108)
NetQ2_B1: Q2.B1 R21.1 U4.3 | length 184.1
  Bottom Layer w8: v1(878.62,101) 929.03,101
  Bottom Layer w10: v1(929.03,82.59) 929.03,101 929.03,149.41 950.3,170.68 950.3,180.68 958.62,189 v1(973.62,189)
NetQ2_B2: Q2.B2 R20.2 U4.2 | length 120.2
  Top Layer w10: Q2.B2@954.62,82.59 979.25,82.59 R20.2@987.66,91 R20.2@987.66,91 v1(987.7,122.92)
  Bottom Layer w10: v1(973.94,169) 973.94,136.69 v1(987.7,122.92)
